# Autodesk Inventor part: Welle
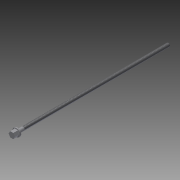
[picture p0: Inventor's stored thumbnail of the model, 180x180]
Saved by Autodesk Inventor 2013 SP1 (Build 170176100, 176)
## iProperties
Created: 2012-11
Part Number: Welle
Material: Allgemein
Document SubType Name: Modeling
Designer: s0536599
Density: 1 g/cm^3
Author: s0536599
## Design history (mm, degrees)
sketch "Skizze1"
  geometry: L1 (0, -16.8)-(0, 16.8) reference; L2 (19.399, 0)-(-19.399, 0) reference; L3 (-13.856, 0)-(-6.928, 12); L4 (-6.928, 12)-(6.928, 12); L5 (6.928, 12)-(13.856, 0); L6 (13.856, 0)-(6.928, -12); L7 (6.928, -12)-(-6.928, -12); L8 (-6.928, -12)-(-13.856, 0); C1 r 6 at (0, 0); 2 further points
  constraints: 12 end point, 2 coincident, 1 centre point, 1 point on line, 13 other
  dimensions: "d0" = 12 diameter of C1; "d1" = 24 distance of L3.end L7.end
extrude "Extrusion1" new body sketch "Skizze1" distance "d2" = 20; taper "d3" = 0 deg
sketch "Skizze2"
  geometry: C1 r 6 at (0, 0) reference; C2 r 17.5 at (0, 0)
  constraints: 1 centre point, 1 coincident
  dimensions: "d4" = 35 diameter of C2
extrude "Extrusion2" join sketch "Skizze2" distance "d7" = 5; taper "d8" = 0 deg
sketch "Skizze3"
  geometry: C1 r 8 at (0, 0); 1 further point
  constraints: 1 centre point, 1 coincident
  dimensions: "d17" = 16 diameter of C1
extrude "Extrusion3" join sketch "Skizze3" distance "d9" = 700; taper "d10" = 0 deg
fillet "Rundung1" dims "d13" = 2
feature "Gewinde2" dims "d18" = 650, "d19" = 0
node "Volumenkörper1"
